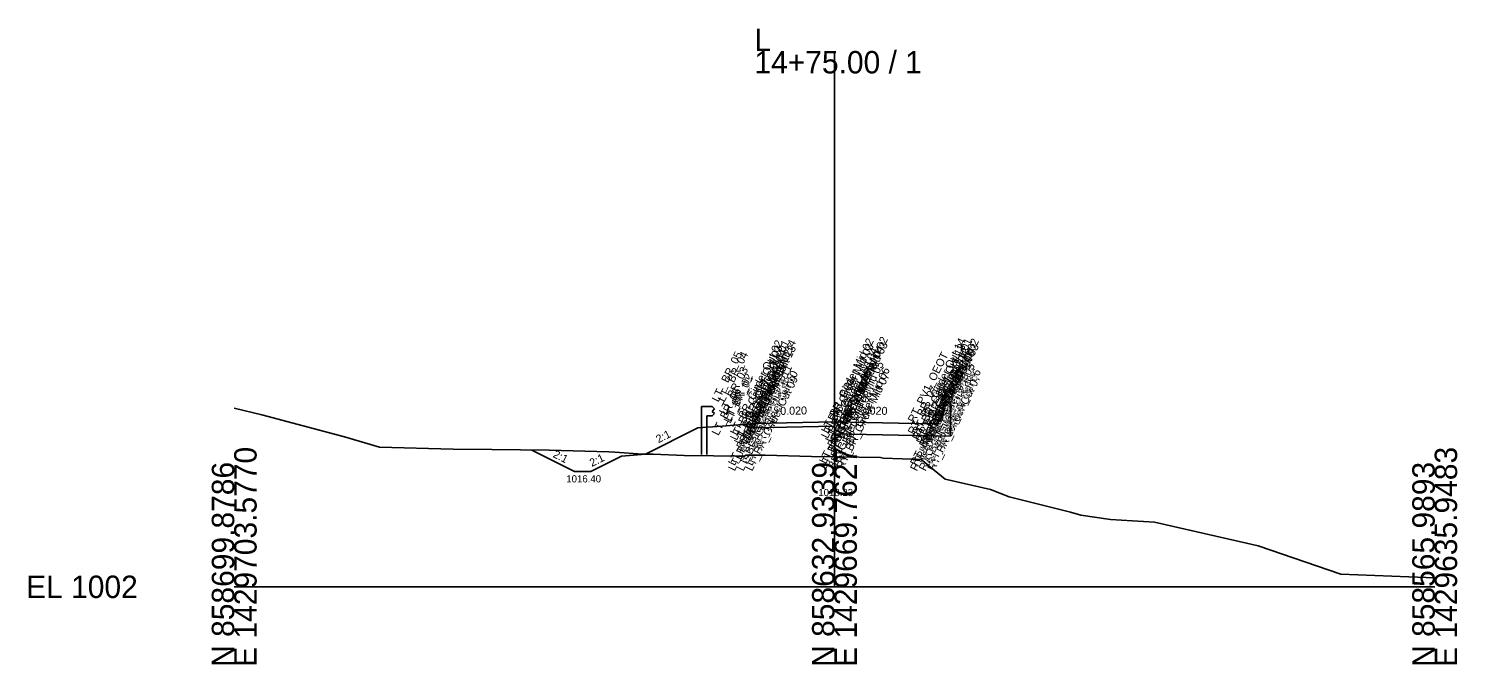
# Model space of a CAD drawing. Extents: x -26 to 153, y -10 to 13058.
# Drawn here: x -25.7 to 152.8, y 6490.3 to 6569.7 of the extents above; entities that cross this region are included whole.
import ezdxf

# ---------------------------------------------------------------- set-up
doc = ezdxf.new("R2010")
doc.units = 0
for name, color, linetype in [('Default', 7, 'Continuous'), ('Exist Cross Section Cell', 7, 'Continuous'), ('Exist XS Center Line Elevation Label', 7, 'Continuous'), ('Exist XS Ground Line', 7, 'Continuous'), ('Prop CMT Concrete Structures', 7, 'Continuous'), ('Prop CMT Guardrail Graphics', 7, 'Continuous'), ('Prop CMT Pvmt Course 1', 7, 'Continuous'), ('Prop CMT Pvmt Surface', 7, 'Continuous'), ('Prop CMT Pvmt Surface Shoulder', 7, 'Continuous'), ('Prop CMT Shld Paved Course 1', 7, 'Continuous'), ('Prop CMT Slope Grass', 7, 'Continuous'), ('Prop CMT Subgrade Earthwork', 7, 'Continuous'), ('Prop XS Dump Level', 7, 'Continuous'), ('Prop XS SE Text', 7, 'Continuous'), ('Prop XS Side Slope Text', 7, 'Continuous')]:
    doc.layers.add(name, color=color, linetype=linetype)

msp = doc.modelspace()

# ---------------------------------------------------------------- linework, layer by layer
at = {"layer": 'Exist Cross Section Cell'}
for p, q in [((75, 6500), (75, 6566.93)), ((0, 6500), (75, 6500)), ((75, 6500), (150, 6500))]:
    msp.add_line(p, q, dxfattribs=at)
at = {"layer": 'Exist XS Ground Line'}
msp.add_lwpolyline([(0, 6522.31), (3.44, 6521.49), (13.79, 6518.72), (18.17, 6517.45), (27.35, 6517.18), (32.2, 6517.15), (39.36, 6517.05), (46.79, 6516.88), (47.56, 6516.84), (51.03, 6516.57), (52.33, 6516.56), (56.24, 6516.42), (59.9, 6516.38), (62.96, 6516.34), (63.78, 6516.33), (63.92, 6516.46), (66.35, 6516.43), (72.14, 6516.29), (75, 6516.23), (75.38, 6516.22), (80.77, 6516.15), (81.07, 6516.09), (85.84, 6515.89), (88.82, 6513.45), (94.51, 6512.15), (96.84, 6511.22), (104.48, 6509.34), (105.79, 6508.93), (109.51, 6508.39), (114.97, 6508.07), (127.95, 6505.12), (138.29, 6501.59), (146.77, 6501.25), (150, 6501.11)], dxfattribs=at)
at = {"layer": 'Prop CMT Concrete Structures'}
for points in [[(75, 6520.61), (85, 6520.41), (88, 6520.35), (88.01, 6520.6), (88.59, 6521.43), (88.76, 6523.01), (89.5, 6523.01), (89.5, 6518.82)], [(75, 6519.11), (75, 6520.61)], [(75, 6519.11), (75, 6520.61)], [(89.5, 6518.82), (85, 6518.91), (75, 6519.11)]]:
    msp.add_lwpolyline(points, dxfattribs=at)
at = {"layer": 'Prop CMT Guardrail Graphics'}
for points in [[(58.4, 6516.51), (58.4, 6522.51)], [(58.4, 6522.51), (59.73, 6522.51), (60, 6522.22)], [(60, 6522.22), (59.73, 6521.92)], [(59.73, 6521.92), (60, 6521.63)], [(60, 6521.63), (59.73, 6521.34), (59.06, 6521.34)], [(59.06, 6521.34), (59.06, 6516.51)]]:
    msp.add_lwpolyline(points, dxfattribs=at)
at = {"layer": 'Prop CMT Pvmt Course 1'}
msp.add_line((75, 6520.61), (75, 6516.23), dxfattribs=at)
for points in [[(75, 6520.61), (65, 6520.41)], [(65, 6520.41), (65, 6519.87)], [(65, 6519.87), (75, 6520.07)]]:
    msp.add_lwpolyline(points, dxfattribs=at)
at = {"layer": 'Prop CMT Pvmt Surface'}
msp.add_lwpolyline([(75, 6520.61), (65, 6520.41)], dxfattribs=at)
at = {"layer": 'Prop CMT Pvmt Surface Shoulder'}
msp.add_lwpolyline([(65, 6520.41), (65, 6520.41)], dxfattribs=at)
at = {"layer": 'Prop CMT Shld Paved Course 1'}
for points in [[(65, 6520.41), (64.45, 6519.85)], [(65, 6520.41), (65, 6520.41)], [(65, 6519.87), (65, 6520.41)], [(64.45, 6519.85), (65, 6519.87)]]:
    msp.add_lwpolyline(points, dxfattribs=at)
at = {"layer": 'Prop CMT Slope Grass'}
for p, q in [((42.54, 6514.4), (37.18, 6517.08)), ((51.39, 6516.57), (48.39, 6516.33)), ((44.54, 6514.4), (48.39, 6516.33)), ((44.54, 6514.4), (42.54, 6514.4))]:
    msp.add_line(p, q, dxfattribs=at)
for points in [[(60.95, 6520.08), (57.95, 6519.84)], [(65, 6520.41), (60.95, 6520.08)], [(57.95, 6519.84), (51.39, 6516.57)]]:
    msp.add_lwpolyline(points, dxfattribs=at)
at = {"layer": 'Prop CMT Subgrade Earthwork'}
for points in [[(64.45, 6519.85), (63.98, 6520.33)], [(75, 6520.07), (65, 6519.87)], [(65, 6519.87), (64.45, 6519.85)]]:
    msp.add_lwpolyline(points, dxfattribs=at)

# ---------------------------------------------------------------- texts
at = {"layer": 'Default'}
for s, height, p in [('1016.40', 0.9, (41.49, 6513.04)), ('-', 0.0001, (0, 6500))]:
    msp.add_text(s, height=height, dxfattribs=at).set_placement(p)
at = {"layer": 'Exist Cross Section Cell'}
for s, p in [('L', (65, 6566.93)), ('14+75.00 / 1', (65, 6564.13)), ('EL 1002', (-26, 6498.6))]:
    msp.add_text(s, height=2.8, dxfattribs=at).set_placement(p)
for s, p in [('E 1429703.5770', (2.8, 6490)), ('E 1429669.7627', (77.8, 6490)), ('E 1429635.9483', (152.8, 6490)), ('N 858699.8786', (0, 6490)), ('N 858632.9339', (75, 6490)), ('N 858565.9893', (150, 6490))]:
    msp.add_text(s, height=2.8, rotation=90, dxfattribs=at).set_placement(p)
at = {"layer": 'Exist XS Center Line Elevation Label'}
msp.add_text('1018.23', height=0.9, dxfattribs=at).set_placement((72.98, 6511.33))
msp.add_text('1018.23', height=0.9, dxfattribs=at).set_placement((72.98, 6511.33))
msp.add_text('1018.23', height=0.9, dxfattribs=at).set_placement((72.98, 6511.33))
at = {"layer": 'Prop XS Dump Level'}
for s, p in [('LT_BR_Girder Out 02', (62.79, 6518.86)), ('LT_BR_Girder Out 14', (64.46, 6518.9)), ('LT_BR_Girder Mid 02', (74.17, 6519.09)), ('RT_BR_Girder Mid 02', (75.83, 6519.09)), ('RT_BR_Girder Out 14', (85.54, 6518.9)), ('RT_BR_Girder Out 01', (86.38, 6518.88)), ('RT_BR_Girder Out 02', (87.21, 6518.86)), ('LT_ BR_05', (60.5, 6523.01)), ('LT_ BR_04', (61.24, 6523.01)), ('LT_BR_Girder Out 03', (62.79, 6518.21)), ('LT_BR_Girder Out 04', (63.29, 6517.71)), ('LT_BR_Girder Out 01', (63.62, 6518.88)), ('LT_BR_Girder Out 12', (63.96, 6517.71)), ('LT_BR_Girder Out 13', (64.46, 6518.21)), ('LT_PV1_OEOT', (65, 6520.41)), ('LT_BR_Girder Mid 03', (74.17, 6518.44)), ('LT_BR_Girder Mid 04', (74.67, 6517.94)), ('RT_BR_Girder Mid 04', (75.33, 6517.94)), ('RT_BR_Girder Mid 03', (75.83, 6518.44)), ('RT_PV1_OEOT', (85, 6520.41)), ('RT_BR_Girder Out 13', (85.54, 6518.21)), ('RT_BR_Girder Out 12', (86.04, 6517.71)), ('RT_BR_Girder Out 04', (86.71, 6517.71)), ('RT_BR_Girder Out 03', (87.21, 6518.21)), ('RT_ BR_04', (88.76, 6523.01)), ('RT_ BR_05', (89.5, 6523.01)), ('LT_BR_03', (61.41, 6521.43)), ('LT_BR_Girder Out 05', (63.29, 6515.8)), ('LT_BR_Girder Out 11', (63.96, 6515.8)), ('LT_BR_Girder Mid 06', (73.92, 6515.27)), ('LT_BR_Girder Mid 05', (74.67, 6516.02)), ('RT_BR_Girder Mid 05', (75.33, 6516.02)), ('RT_BR_Girder Mid 06', (76.08, 6515.27)), ('RT_BR_Girder Out 10', (85.29, 6515.05)), ('RT_BR_Girder Out 11', (86.04, 6515.8)), ('RT_BR_Girder Out 05', (86.71, 6515.8)), ('RT_BR_Girder Out 06', (87.46, 6515.05)), ('RT_BR_03', (88.59, 6521.43)), ('LT_BR_02', (61.99, 6520.6)), ('LT_BR_01', (62, 6520.35)), ('LT_BR_Girder Out 06', (62.54, 6515.05)), ('LT_BR_Girder Out 07', (62.54, 6514.38)), ('LT_BR_Girder Out 08', (63.62, 6514.38)), ('LT_BR_Girder Out 10', (64.71, 6515.05)), ('LT_BR_Girder Out 09', (64.71, 6514.38)), ('LT_BR_Girder Mid 07', (73.92, 6514.61)), ('PV1_PGL', (75, 6520.61)), ('RT_BR_Girder Mid 07', (76.08, 6514.61)), ('RT_BR_Girder Out 09', (85.29, 6514.38)), ('RT_BR_Girder Out 08', (86.38, 6514.38)), ('RT_BR_Girder Out 07', (87.46, 6514.38)), ('RT_BR_01', (88, 6520.35)), ('RT_BR_02', (88.01, 6520.6)), ('LT_BR_06', (60.5, 6518.82)), ('LT_BR_07', (65, 6518.91)), ('BR_Girder Mid 08', (75, 6514.61)), ('BR_PGL', (75, 6519.11)), ('RT_BR_07', (85, 6518.91)), ('RT_BR_06', (89.5, 6518.82))]:
    msp.add_text(s, height=1, rotation=63.5833, dxfattribs=at).set_placement(p)
at = {"layer": 'Prop XS SE Text'}
for rotation, p in [(1.1458, (68.23, 6521.47)), (1.1458, (68.23, 6521.47)), (358.8542, (78.27, 6521.54))]:
    msp.add_text('0.020', height=1, rotation=rotation, dxfattribs=at).set_placement(p)
at = {"layer": 'Prop XS Side Slope Text'}
for rotation, p in [(26.5651, (53, 6517.92)), (333.4349, (39.74, 6516.24)), (26.5651, (44.7, 6514.96))]:
    msp.add_text('2:1', height=1, rotation=rotation, dxfattribs=at).set_placement(p)

doc.saveas('drawing.dxf')
